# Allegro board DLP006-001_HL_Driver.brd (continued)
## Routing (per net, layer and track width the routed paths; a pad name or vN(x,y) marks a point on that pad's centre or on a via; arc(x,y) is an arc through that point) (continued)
N68109: length 2.3
  TOP w0.254: R31.1 43.69,48.51 43.98,48.81 U4.6
N68463: length 3.8
  TOP w0.254: D7.C 41.17,59.18 C33.2 42.03,57.18 U4.26
N68698: length 3.5
  TOP w0.254: D8.C 45.85,58.19 C32.2 45.97,58.02 45.97,56.79 45.93,56.76 U4.20
N69433: length 1.4
  TOP w0.381: Q6.4 33.94,68.95 R5.2
N70256: length 1.6
  TOP w0.254: Q4.4 40.82,67.31 41.66,68.15 R14.2
N70284: length 7.4
  TOP w0.254: R17.1 49.4,63.88 49.4,63.12 48.38,62.09 48.38,60.72 49.28,59.82 R20.2
  vias: v1(38.35,66.17) v1(39.75,66.17) v1(39.75,64.9) v1(39.75,63.5) v1(40.89,65.53) v1(40.89,64.14) v1(42.29,64.64) v1(42.29,63.12) v1(44.07,64.14) v1(44.07,62.99) v1(45.09,66.29) v1(45.09,64.14) v1(45.09,62.99) v1(46.1,62.99) v1(46.99,66.8) v1(49.53,67.31) v1(50.42,66.55) v1(52.2,66.42)
N70639: length 1.2
  TOP w0.254: R12.2 54.37,69.09 Q7.4
N70965: length 1
  TOP w0.254: R4.2 46.32,68.72 C17.2
N71936: length 1.2
  TOP w0.254: R15.2 C13.2
N87249: length 5.6
  TOP w0.254: R7.2 71.87,68.82 72.67,69.62 R10.1 74.18,69.62 C14.2 74.3,70.61 74.43,70.75 U1.2
N87366: length 3
  TOP w0.254: U1.7 77.68,70.78 78.36,70.1 C16.2
N87373: length 2.6
  TOP w0.254: U1.5 76.38,70.95 76.58,70.75 76.58,70.74 77.09,70.23 C15.2
N87380: length 2.4
  TOP w0.254: R8.1 75.18,70.64 75.08,70.74 U1.3
N87387: length 2.6
  TOP w0.254: U1.16 76.38,79.32 76.71,79.64 C5.2
N87394: length 2.5
  TOP w0.254: U1.17 75.73,80.45 C4.2
N87932: length 12
  TOP w0.254: v1(73.53,81.03) 73.53,80.28 C6.1 73.52,79.51 73.78,79.25 U1.20
  BOTTOM w0.254: v1(73.53,81.03) 72.64,81.92 v1(72.64,89.53)
N88013: length 24.1
  TOP w0.254: R1.1 v1(68.2,98.3) ; v1(74.43,79.38) U1.19
  BOTTOM w0.254: v1(68.2,98.3) 68.2,84.71 73.53,79.38 v1(74.43,79.38)
N88019: length 2.4
  TOP w0.254: U1.18 75.08,79.74 C6.2
N88053: length 19
  TOP w0.254: 73.85,84.9 R2.1 74.8,84.84 75.06,85.09 v1(75.06,86.11)
  TOP w0.305: v1(79.38,79.5) 78.99,79.12 78.99,78.04 U1.12
  TOP w0.762: D3.1 67.18,86.23 ; D3.2 68.45,86.23 ; D3.3 69.72,86.23
  BOTTOM w0.254: v1(79.38,79.5) 79.12,79.76 79.12,82.42 77.72,83.82 77.72,86.74 77.09,87.38 75.69,87.38 75.06,86.74 v1(75.06,86.11)
N88776: length 2.8
  TOP w0.762: D4.1 86.49,81.03 ; 83.95,80.09 83.95,81.03 ; D4.2 85.22,81.03
N88824: length 4.1
  TOP w0.254: R3.2 79.39,80.66 81.96,83.23 Q2.4
N88961: length 6.2
  TOP w0.254: R11.2 81.74,68.07 81.28,68.07 R13.1 80.62,68.55 R6.1 80.06,69.06 C12.2 78.99,70.14 78.99,70.35 78.33,71.01 U1.8
N89225: length 3.6
  TOP w0.254: U1.9 78.98,71 79.25,70.74 79.86,70.74 C12.1 80.96,71.06 C10.1
N89343: length 1.6
  TOP w0.254: C10.2 81.58,69.47 81.18,69.47 R6.2
N14686613: length 1.3
  TOP w0.254: Q5.4 53.05,66.09 R16.2
N14713667: length 8.5
  TOP w0.381: U2.6 16.57,70.29 17.21,70.94 U2.2 17.21,74.36 17.91,75.06 Q3.4
N14713719: length 4.2
  TOP w0.381: 15.92,73.53 U2.4
  TOP w0.508: 15.92,74.55 15.92,73.53
  TOP w1.016: 15.92,76.54 15.92,74.55
  vias: v1(9.78,89.15) v1(9.78,87.5) v1(9.78,85.72) v1(9.78,84.07) v1(9.78,82.42) v1(9.78,80.77) v1(9.78,79.12) v1(11.3,89.15) v1(11.3,87.5) v1(11.3,85.72) v1(11.3,84.07) v1(11.3,82.42) v1(11.3,80.77) v1(11.3,79.12) v1(12.7,89.15) v1(12.7,87.5) v1(12.7,85.72) v1(12.7,84.07) v1(12.7,82.42) v1(12.7,80.77) v1(12.7,79.12) v1(14.22,80.77) v1(14.22,79.12) v1(15.75,80.77) v1(15.75,79.12) v1(17.14,80.77) v1(17.14,79.12)
N14713759: length 3.6
  TOP w0.381: C11.1 17.5,69.7 17.21,69.41 U2.7
N14725098: length 4.7
  TOP w0.254: R47.2 9.68,32.91 9.7,32.93 R44.2 10.54,32.93 11.09,32.38 C54.2 12.73,32.38 13.04,32.07 U5.2
N14726673: length 4.9
  TOP w0.254: R48.2 41.5,32.91 41.53,32.93 R45.2 42.42,32.93 42.96,32.38 C55.2 44.6,32.38 44.9,32.09 45.14,32.09 45.15,32.07 U6.2
N14726919: length 4.9
  TOP w0.254: R49.2 73.3,32.91 73.33,32.93 R46.2 74.3,32.93 74.84,32.38 C56.2 76.48,32.38 76.78,32.09 76.88,32.09 76.89,32.07 U7.2
N14728608:
  vias: v1(18.54,27.43) v1(18.54,25.15) v1(18.54,23.11) v1(18.54,20.83) v1(18.8,18.54) v1(18.8,17.27) v1(19.3,26.16) v1(20.07,27.43) v1(20.07,25.15) v1(20.57,18.54) v1(20.57,17.27) v1(20.83,26.16) v1(21.59,27.43) v1(21.59,25.15) v1(22.35,26.16) v1(22.35,18.54) v1(22.35,17.27) v1(23.11,27.43) v1(23.11,25.15) v1(23.37,23.11) v1(23.37,20.83) v1(23.37,19.3) v1(23.62,17.78) v1(24.89,20.83) v1(24.89,19.43) v1(24.89,18.03) v1(24.89,16.76) v1(26.67,20.83) v1(26.67,19.43) v1(28.32,20.83) v1(28.32,19.43) v1(29.72,20.83) v1(29.72,19.43) v1(30.99,20.07) v1(31.24,18.54) v1(31.24,17.02)
N14729090:
  vias: v1(50.29,27.43) v1(50.29,25.15) v1(50.29,23.11) v1(50.29,20.83) v1(50.55,18.54) v1(50.55,17.27) v1(51.05,26.29) v1(51.82,27.43) v1(51.82,25.15) v1(52.32,18.54) v1(52.32,17.27) v1(52.58,26.29) v1(53.34,27.43) v1(53.34,25.15) v1(54.1,26.29) v1(54.1,18.54) v1(54.1,17.27) v1(54.86,27.43) v1(54.86,25.15) v1(55.12,23.11) v1(55.12,20.83) v1(55.12,19.3) v1(55.37,17.78) v1(56.64,20.83) v1(56.64,19.43) v1(56.64,18.03) v1(56.64,16.76) v1(58.42,20.83) v1(58.42,19.43) v1(60.07,20.83) v1(60.07,19.43) v1(61.47,20.83) v1(61.47,19.43) v1(62.74,20.07) v1(62.99,18.54) v1(62.99,17.02)
N14729291:
  vias: v1(82.3,27.43) v1(82.3,25.15) v1(82.3,23.11) v1(82.3,20.83) v1(82.55,18.54) v1(82.55,17.27) v1(83.06,26.16) v1(83.82,27.43) v1(83.82,25.15) v1(84.33,18.54) v1(84.33,17.27) v1(84.58,26.16) v1(85.34,27.43) v1(85.34,25.15) v1(86.11,26.16) v1(86.11,18.54) v1(86.11,17.27) v1(86.87,27.43) v1(86.87,25.15) v1(87.12,23.11) v1(87.12,20.83) v1(87.12,19.3) v1(87.38,17.78) v1(88.65,20.83) v1(88.65,19.43) v1(88.65,18.03) v1(88.65,16.76) v1(90.42,20.83) v1(90.42,19.43) v1(92.08,20.83) v1(92.08,19.43) v1(93.47,20.83) v1(93.47,19.43) v1(94.74,20.07) v1(95,18.54) v1(95,17.02)
N14733774: length 1.8
  TOP w0.254: R24.1 17.21,50.24 U3.3
N14733778: length 1.8
  TOP w0.254: U3.2 R23.1
N14755460: length 2.2
  TOP w0.381: U2.1 19.01,72.3 19.18,72.14 C11.2
N14772112:
  vias: v1(13.46,98.04) v1(13.46,96.52) v1(15.11,98.04) v1(15.11,96.52) v1(18.8,98.04) v1(18.8,96.52) v1(20.45,98.04) v1(20.45,96.52)
N14778799: length 29
  TOP w0.254: U1.4 75.73,70.83 75.95,70.61 v1(75.95,70.48) 76.07,70.36 R9.2
  TOP w0.508: SW1.5 v1(91.19,84.32)
  BOTTOM w0.508: v1(91.19,84.32) 91.19,77.47 84.2,70.48 v1(75.95,70.48)
N14789264: length 1.1
  TOP w0.254: C65.1 R61.2
N14790575: length 1.1
  TOP w0.254: C63.1 R59.2
N14791153: length 1.1
  TOP w0.254: C64.1 R60.2
N14801227: length 0.9
  TOP w0.254: C71.1 R64.2
N14802192: length 3
  TOP w0.254: U4.14 49.18,49.06 49,48.88 48.68,48.88 48.53,49.02 U4.13
N14805188: length 19.9
  TOP w0.508: v1(97.44,20.45) Q10.1 ; R58.2 v1(84.82,29.4)
  BOTTOM w0.508: v1(97.44,20.45) 97.44,21.18 89.22,29.4 v1(84.82,29.4)
N14810522: length 19.5
  TOP w0.508: R57.2 v1(52.95,29.4) ; Q9.1 v1(65.57,20.67)
  BOTTOM w0.508: v1(52.95,29.4) 57.47,29.4 65.57,21.3 v1(65.57,20.67)
N14810532: length 20.1
  TOP w0.508: v1(33.69,20.45) Q8.1 ; v1(21.21,29.4) R56.2
  BOTTOM w0.508: v1(33.69,20.45) 33.69,21.56 25.84,29.4 v1(21.21,29.4)
N14814395: length 0.9
  TOP w0.254: C70.1 R63.2
N14818963: length 2.3
  TOP w0.254: J5.7 7.07,55.59 L8.1
N14818967: length 2.3
  TOP w0.254: J5.8 7.05,56.59 L7.1
N14818971: length 2.3
  TOP w0.254: J5.9 7.04,57.59 L6.1
N14901904: length 0.9
  TOP w0.254: C69.1 R62.2
N15037743: length 2.3
  TOP w0.254: C45.2 45.59,48.59 45.28,48.9 U4.8
N15077521: length 1.4
  TOP w0.254: Q1.4 66.41,96.89 R1.2

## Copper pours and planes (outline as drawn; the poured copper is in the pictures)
16V_REG on TOP (solid shape): 57.68,65.53 55.35,65.53 55.35,68.12 57.68,68.12
16V_REG on TOP: 58.93,67.44 58.17,68.2 55.37,68.2 54.99,67.82 54.99,63.63 55.63,62.99 66.04,62.99 68.83,60.2 77.85,60.2 77.85,65.79 77.09,66.55 61.59,66.55 60.71,67.44
16V_REG on TOP: 18.52,33.78 17.96,33.22 17.96,32.46 19.18,32.46 19.49,32.77 27.89,32.77 31.11,35.99 31.11,37.08 27.75,40.44 26.87,40.44 24.04,37.62 19.96,37.62 19.59,37.24 19.59,34.3 19.07,33.78
16V_REG on TOP: 51.45,34.84 49.83,33.22 49.83,32.46 51.09,32.46 51.39,32.77 59.77,32.77 62.99,35.99 62.99,37.08 59.49,40.58 58.89,40.58 55.92,37.62 51.99,37.62 51.45,37.07
16V_REG on TOP: 83.32,34.83 81.71,33.22 81.71,32.46 83.13,32.46 83.44,32.77 91.64,32.77 94.87,35.99 94.87,36.07 96.52,36.07 99.06,38.61 99.06,39.37 96.9,41.53 95.89,41.53 94.61,40.26 89.92,40.26 87.27,37.62 83.72,37.62 83.32,37.22
16V_REG on BOTTOM: 25.91,42.67 21.97,38.73 19.56,38.73 17.91,37.08 17.91,33.27 18.54,32.64 32.89,32.64 33.91,33.66 33.91,40.13 31.37,42.67
16V_REG on BOTTOM: 54.48,39.24 52.45,39.24 47.88,34.67 47.88,33.5 49.89,31.5 65.66,31.5 67.31,33.15 67.31,35.81 60.83,42.29 57.53,42.29
16V_REG on BOTTOM: 76.33,66.55 63.5,66.55 63.25,66.29 63.25,63.5 63.5,63.25 76.2,63.25 76.71,63.75 76.71,66.17
16V_REG on BOTTOM: 86.87,38.23 83.69,38.23 79.76,34.29 79.76,33.5 81.76,31.5 97.28,31.5 99.31,33.53 99.31,42.16 98.93,42.55 91.19,42.55
16V_REG on L3_PWR: 29.84,32.51 31.11,33.78 52.07,33.78 53.59,32.26 60.2,32.26 62.1,34.16 83.44,34.16 85.34,32.26 99.31,32.26 99.31,40.77 89.66,50.42 89.66,65.15 86.61,68.2 56.13,68.2 48.9,60.96 19.18,60.96 19.18,48.26 12.83,41.91 12.83,33.66 13.97,32.51
GND_SIGNAL on TOP: outline of 87 points within 0.51,0.76 97.66,45.72
GND_SIGNAL on TOP: 75.31,29.21 75.31,30.35 75.95,30.35 76.33,30.73 78.11,30.73 78.11,36.83 77.85,37.08 76.83,37.08 76.57,36.82 76.57,34.02 76.33,33.78 73.53,33.78 73.53,37.08 65.28,45.34 53.59,45.34 52.07,46.86 52.07,50.55 51.31,51.31 49.66,51.31 49.66,54.61 50.8,54.61 51.05,54.86 51.05,59.56 49.85,60.77 52.51,63.44 53.98,61.98 66.04,61.98 66.04,59.56 67.69,57.91 77.72,57.91 78.36,58.55 78.36,66.17 77.98,66.55 77.98,68.07 80.01,68.07 80.77,67.31 83.82,67.31 83.82,46.35 95,46.35 96.9,44.45 96.9,43.94 94.9,41.94 93.19,41.94 93.19,41.93 89.05,41.93 85.72,38.61 83.44,38.61 81.41,36.58 81.41,29.46 81.15,29.21
GND_SIGNAL on TOP: 21.59,61.98 38.35,61.98 38.73,61.59 38.73,55.17 39.29,54.61 40.16,54.61 40.13,54.58 40.13,51.28 38.61,51.28 38.61,49.91 37.59,49.91 37.47,50.04 37.47,51.03 37.21,51.28 28.4,51.28 26.34,53.34 21.46,53.34 20.95,53.85 20.95,61.34
GND_SIGNAL on TOP: 32.77,94.49 32.77,97.28 33.4,97.92 36.7,97.92 37.47,97.16 37.47,94.87 35.56,94.87 35.18,94.49
GND_SIGNAL on TOP: 12.57,30.73 14.35,30.73 14.35,36.96 14.1,37.21 13.08,37.21 12.81,36.94 12.81,34.02 12.57,33.78 9.91,33.78 9.91,37.21 16.64,43.94 24.26,43.94 25.53,42.67 25.53,42.16 21.97,38.61 19.68,38.61 17.65,36.58 17.65,29.46 17.4,29.21 11.56,29.21 11.56,30.35 12.19,30.35
GND_SIGNAL on TOP: 42.55,46.61 42.16,46.23 42.16,44.96 42.42,44.7 47.62,44.7 47.75,44.83 47.75,45.34 47.37,45.34 47.12,45.59 47.12,46.35 46.86,46.61
GND_SIGNAL on TOP: 1.02,97.54 1.02,78.99 1.52,78.49 5.71,78.49 8.89,75.31 10.54,75.31 10.54,76.07 7.11,79.5 7.11,92.33 8,93.22 11.05,93.22 11.05,94.74 9.53,96.27 9.53,97.66 1.14,97.66
GND_SIGNAL on TOP: 44.45,30.73 46.23,30.73 46.23,36.83 45.97,37.08 44.96,37.08 44.69,36.82 44.69,34.02 44.45,33.78 41.66,33.78 41.66,42.42 43.05,43.81 56.26,43.81 57.4,42.67 57.4,42.16 53.85,38.61 51.56,38.61 49.53,36.58 49.53,29.46 49.28,29.21 43.69,29.21 43.31,29.59 43.31,30.35 44.07,30.35
GND_SIGNAL on TOP: 81.41,83.69 82.68,83.69 82.68,86.74 82.17,87.25 78.11,87.25 76.58,85.72 76.58,83.82 76.33,83.57 70.87,83.57 69.72,82.42 69.72,74.93 70.99,73.66 81.66,73.66 81.66,76.45 73.41,76.45 72.9,76.96 72.9,81.28 73.28,81.66 79.38,81.66
GND_SIGNAL on BOTTOM: 0.51,96.65 0.51,80.01 2.03,78.49 8,78.49 8,90.55 10.92,93.47 10.92,98.81 10.16,99.57 3.43,99.57
GND_SIGNAL on BOTTOM: 37.21,59.82 34.67,59.82 34.42,59.56 34.42,53.47 37.47,50.42 49.15,50.42 50.29,51.56 50.29,54.23 49.02,55.5 41.53,55.5
GND_SIGNAL on BOTTOM: 29.21,59.05 25.4,62.87 15.24,62.87 14.61,62.23 14.61,55.24 21.59,48.26 27.3,48.26 29.21,50.16
GND_SIGNAL on BOTTOM: 51.94,59.56 51.94,45.09 61.21,45.09 72.77,33.53 78.36,33.53 83.57,38.73 86.61,38.73 90.93,43.05 98.17,43.05 99.31,44.2 99.31,97.16 97.03,99.44 74.68,99.44 73.41,98.17 73.41,88.52 74.04,87.88 77.6,87.88 78.23,87.25 78.23,83.95 80.14,82.04 80.14,79.12 79.5,78.49 71.75,78.49 71.25,77.98 71.25,74.68 72.77,73.15 72.77,70.23 71.63,69.09 58.42,69.09 56.52,67.18 56.52,64.14
GND_SIGNAL on BOTTOM: 85.47,3.68 84.84,3.05 73.28,3.05 68.96,7.37 68.96,14.35 67.18,16.13 54.1,16.13 53.59,15.62 53.59,4.19 52.58,3.17 40.89,3.17 36.7,7.37 36.7,14.61 35.18,16.13 22.23,16.13 21.72,15.62 21.72,3.81 20.83,2.92 20.7,3.05 9.14,3.05 4.95,7.24 4.95,64.52 4.45,65.02 1.27,65.02 0.76,64.52 0.76,3.17 3.17,0.76 96.9,0.76 99.31,3.17 99.31,15.24 98.42,16.13 86.11,16.13 85.47,15.49
GND_SIGNAL on BOTTOM: 56.52,43.94 35.94,43.94 34.92,42.93 34.92,36.58 36.07,35.43 38.73,35.43 41.02,33.15 45.72,33.15 52.2,39.62 54.36,39.62 57.02,42.29 57.02,43.43
GND_SIGNAL on L2_GND: 0.76,99.31 99.31,99.31 99.31,0.64 0.76,0.64
GND_SIGNAL on L3_PWR: 0.76,99.31 99.31,99.31 99.31,0.64 0.76,0.64 ; 5 cut-outs
VBATT on TOP, BOTTOM: 13.84,74.3 7.87,74.3 4.95,77.22 1.52,77.22 1.14,76.83 1.14,66.42 1.91,65.66 13.97,65.66 14.35,66.04 14.35,73.79
VBATT on L3_PWR: 13.84,77.22 0.76,77.22 0.76,65.66 13.97,65.66 14.35,66.04 14.35,76.71
VIN_HEATER on TOP: 50.42,92.71 44.32,92.71 43.69,93.34 43.69,96.52 44.32,97.16 50.93,97.16 50.93,93.22
VIN_HEATER on BOTTOM: 49.66,97.03 48.77,97.92 44.58,97.92 43.69,97.03 43.69,92.08 44.32,91.44 48.64,91.44 49.66,92.46
VIN_MAIN on TOP: 30.86,93.85 40.39,93.85 40.39,91.19 39.12,89.92 31.75,89.92 30.86,90.81
VIN_MAIN on BOTTOM: 40.13,93.85 33.15,93.85 31.5,92.2 31.5,90.04 32.26,89.28 39.12,89.28 40.13,90.3
SW1 on TOP (solid shape): 40.67,68.28 38.33,68.28 38.33,70.87 40.67,70.87
SW1 on TOP: 44.2,87.63 33.15,87.63 31.11,85.6 31.11,73.28 34.54,69.85 34.54,68.58 37.34,68.58 37.72,68.2 40.89,68.2 41.66,68.96 44.7,68.96 45.72,69.98 46.61,69.98 46.61,70.99 45.09,72.52 45.09,86.74
SW1 on BOTTOM: 43.31,71.25 33.02,71.25 31.37,72.9 31.37,75.56 32,76.2 43.05,76.2 43.94,75.31 43.94,71.88
SW1 on L3_PWR: 44.2,87.63 33.15,87.63 31.11,85.6 31.11,71.63 33.78,68.96 44.7,68.96 45.09,69.34 45.09,86.74
SW2 on TOP (solid shape): 53.24,68.28 50.9,68.28 50.9,70.87 53.24,70.87
SW2 on TOP: 56.01,68.58 56.01,69.98 55.75,70.23 54.1,70.23 53.72,69.85 53.72,68.58 53.47,68.33 50.55,68.33 46.99,71.88 46.99,86.61 48.01,87.63 60.2,87.63 61.34,86.49 61.34,74.8 62.36,73.79 62.36,69.6 61.72,69.6 61.21,69.09 58.8,69.09 58.29,68.58
SW2 on BOTTOM: 61.72,76.07 49.91,76.07 49.28,75.44 49.28,71.5 49.66,71.12 61.98,71.12 62.48,71.63 62.48,75.31
SW2 on L3_PWR: 50.04,68.83 46.99,71.88 46.99,86.61 48.01,87.63 61.85,87.63 62.61,86.87 62.61,69.34 62.1,68.83
V_BATT_PROT on TOP (solid shape): 36.22,65.53 33.88,65.53 33.88,68.12 36.22,68.12
V_BATT_PROT on TOP (solid shape): 21.98,78.95 24.11,78.95 24.11,79.42 24.55,79.42 24.55,74.5 24.11,74.5 24.11,74.97 21.98,74.97 21.98,74.38 21.45,74.38 21.45,74.97 20.53,74.97 20.53,78.95 21.45,78.95 21.45,79.54 21.98,79.54
V_BATT_PROT on TOP (solid shape): 65.68,94.41 62.98,94.41 62.98,95.08 63.47,95.08 63.47,95.39 62.98,95.39 62.98,95.73 63.47,95.73 63.47,96.04 62.98,96.04 62.98,96.39 63.47,96.39 63.47,96.69 62.98,96.69 62.98,97.36 65.68,97.36
V_BATT_PROT on TOP: 21.34,80.26 25.4,80.26 26.42,81.28 26.42,93.98 30.23,93.98 30.23,68.96 30.99,68.2 36.2,68.2 36.96,67.44 36.96,66.04 38.48,64.52 38.48,63.12 38.35,62.99 19.56,62.99 17.65,64.9 17.65,68.58 19.56,68.58 20.55,69.57 20.55,79.48
V_BATT_PROT on TOP: 73.91,72.9 70.48,72.9 67.69,75.69 67.69,83.19 65.53,85.34 65.53,98.68 65.15,99.06 53.34,99.06 51.82,97.54 51.82,92.2 54.1,89.92 58.67,89.92 61.85,86.74 61.85,75.56 62.99,74.42 62.99,71.63 64.9,69.72 71.75,69.72 71.75,70.23 72.77,71.25 73.91,71.25
V_BATT_PROT on TOP: 36.7,49.28 36.7,50.67 36.45,50.93 34.04,50.93 33.53,50.42 33.53,49.53 33.78,49.28
V_BATT_PROT on TOP: 32.13,94.61 32.13,98.42 31.62,98.93 27.05,98.93 26.42,98.3 26.42,93.98 30.23,93.98 30.86,94.61
V_BATT_PROT on BOTTOM: 29.84,92.71 29.84,89.92 31.5,88.27 46.99,88.27 52.2,93.47 52.2,98.3 53.09,99.19 65.02,99.19 65.53,98.68 65.53,85.34 70.55,80.33 70.55,74.49 72.26,72.77 72.26,70.99 71.37,70.1 64.77,70.1 64.14,70.74 64.14,75.18 61.85,77.47 30.48,77.47 29.84,76.83 29.84,71.75 34.04,67.56 34.04,52.96 35.56,51.44 35.56,48.26 34.92,47.62 31.75,47.62 29.84,49.53 29.84,59.05 25.53,63.37 19.3,63.37 18.41,64.26 18.41,73.15 24.13,78.87 24.13,97.16 26.04,99.06 31.75,99.06 32.38,98.42 32.38,95.25
V_BATT_PROT on L3_PWR: 30.48,86.11 30.48,71.75 35.43,66.8 35.43,62.48 34.67,61.72 19.18,61.72 19.18,91.82 26.54,99.19 68.71,99.19 70.87,97.03 70.87,74.3 73.15,72.01 73.15,69.6 72.52,68.96 63.88,68.96 63.25,69.6 63.25,87.38 62.36,88.27 32.64,88.27
V_FAN on TOP (solid shape): 86.86,78.2 87.36,78.2 87.36,77.3 86.86,77.3 86.86,74.1 86.11,74.1 86.11,74.59 83.05,74.59 83.05,74.1 82.3,74.1 82.3,77.3 81.81,77.3 81.81,78.2 82.3,78.2 82.3,78.63 86.86,78.63
V_FAN on TOP: 82.42,78.49 89.92,78.49 93.34,75.06 93.34,47.88 92.71,47.24 86.87,47.24 85.98,48.13 85.98,67.82 82.42,71.37
V_LED_0 on TOP (solid shape): 77.52,9.13 77.05,9.13 77.05,7 77.64,7 77.64,6.47 77.05,6.47 77.05,5.55 73.07,5.55 73.07,6.47 72.48,6.47 72.48,7 73.07,7 73.07,9.13 72.6,9.13 72.6,9.57 77.52,9.57
V_LED_0 on TOP: 71.5,16.76 71.5,4.83 84.45,4.83 84.96,5.33 84.96,8.26 84.2,9.02 84.2,13.34 84.45,13.59 84.96,13.59 84.96,15.29 77.55,15.29 76.58,16.26 76.58,28.14 76.33,28.4 70.87,28.4 70.23,27.76 70.23,18.03
V_LED_0 on BOTTOM: 70.48,28.57 70.1,28.19 70.1,8 73.41,4.7 83.95,4.7 84.96,5.71 84.96,15.49 84.33,16.13 81.79,16.13 79.88,18.03 79.88,27.69 78.99,28.57
V_LED_0 on L3_PWR: 71.5,16.76 71.5,7.87 72.52,6.86 72.52,4.83 84.71,4.83 84.71,8.51 84.2,9.02 84.2,13.34 84.45,13.59 84.96,13.59 84.96,15.29 77.55,15.29 76.58,16.26 76.58,28.14 76.33,28.4 70.87,28.4 70.23,27.76 70.23,18.03
V_LED_1 on TOP (solid shape): 13.76,9.13 13.29,9.13 13.29,7 13.88,7 13.88,6.47 13.29,6.47 13.29,5.55 9.31,5.55 9.31,6.47 8.72,6.47 8.72,7 9.31,7 9.31,9.13 8.84,9.13 8.84,9.57 13.76,9.57
V_LED_1 on TOP: 7.75,16.76 7.75,4.83 20.7,4.83 21.21,5.33 21.21,8.26 20.45,9.02 20.45,13.34 20.7,13.59 21.21,13.59 21.21,15.24 21.16,15.29 13.79,15.29 12.83,16.26 12.83,28.14 12.57,28.4 7.11,28.4 6.48,27.76 6.48,18.03
V_LED_1 on BOTTOM: 6.73,28.57 6.35,28.19 6.35,8.64 10.29,4.7 20.19,4.7 21.21,5.71 21.21,15.49 20.57,16.13 18.03,16.13 16.13,18.03 16.13,27.69 15.24,28.57
V_LED_1 on L3_PWR: 7.75,16.76 7.75,7.87 8.76,6.86 8.76,4.83 20.95,4.83 20.95,8.51 20.45,9.02 20.45,13.34 20.7,13.59 21.21,13.59 21.21,15.24 21.16,15.29 13.79,15.29 12.83,16.26 12.83,28.14 12.57,28.4 7.11,28.4 6.48,27.76 6.48,18.03
V_LED_2 on TOP (solid shape): 45.64,9.13 45.17,9.13 45.17,7 45.76,7 45.76,6.47 45.17,6.47 45.17,5.55 41.19,5.55 41.19,6.47 40.6,6.47 40.6,7 41.19,7 41.19,9.13 40.72,9.13 40.72,9.57 45.64,9.57
V_LED_2 on TOP: 39.62,16.76 39.62,4.83 52.58,4.83 53.09,5.33 53.09,8.26 52.32,9.02 52.32,13.34 52.58,13.59 53.09,13.59 53.09,15.29 45.67,15.29 44.7,16.26 44.7,28.14 44.45,28.4 38.99,28.4 38.35,27.76 38.35,18.03
V_LED_2 on BOTTOM: 38.61,28.57 38.23,28.19 38.23,8 41.53,4.7 52.07,4.7 53.09,5.71 53.09,15.49 52.45,16.13 49.91,16.13 48.01,18.03 48.01,27.69 47.12,28.57
V_LED_2 on L3_PWR: 39.62,16.76 39.62,7.87 40.64,6.86 40.64,4.83 52.83,4.83 52.83,8.51 52.32,9.02 52.32,13.34 52.58,13.59 53.09,13.59 53.09,15.29 45.67,15.29 44.7,16.26 44.7,28.14 44.45,28.4 38.99,28.4 38.35,27.76 38.35,18.03
N57763 on TOP: 30.38,30.45 32.69,32.77 33.15,32.77 35.18,30.73 35.18,25.65 32.38,25.65 32.38,27.94 30.38,29.95
N57763 on BOTTOM: 35.56,30.99 31.75,30.99 30.61,29.84 30.61,27.3 31.11,26.8 36.07,26.8 36.45,27.18 36.45,30.1
N57763 on L3_PWR: 30.38,30.45 31.8,31.88 34.04,31.88 35.18,30.73 35.18,25.65 32.38,25.65 32.38,27.18 30.38,29.18
N60948 on TOP: 62.26,30.45 64.57,32.77 65.02,32.77 67.06,30.73 67.06,25.65 64.26,25.65 64.26,27.94 62.26,29.95
N60948 on BOTTOM: 67.69,30.61 63.88,30.61 62.74,29.46 62.74,26.92 63.25,26.42 68.2,26.42 68.58,26.8 68.58,29.72
N60948 on L3_PWR: 62.26,30.45 63.55,31.75 66.04,31.75 67.06,30.73 67.06,25.65 64.26,25.65 64.26,27.69 62.26,29.69
N64418 on TOP: 94.13,30.45 96.44,32.77 96.9,32.77 98.93,30.73 98.93,25.65 96.14,25.65 96.14,27.94 94.13,29.95
N64418 on BOTTOM: 98.3,30.48 94.49,30.48 93.34,29.34 93.34,26.8 93.85,26.29 98.81,26.29 99.19,26.67 99.19,29.59
N64418 on L3_PWR: 94.13,31.39 94.49,31.75 97.92,31.75 98.93,30.73 98.93,25.65 96.14,25.65 96.14,27.18 94.13,29.18
N66768 on TOP: 37.97,47.24 39.12,47.24 39.5,47.62 39.5,48.9 39.37,49.02 37.97,49.02
N66777 on TOP: 38.48,46.74 35.69,46.74 35.69,45.34 35.81,45.21 37.97,45.21 38.48,45.72
N70284 on TOP: 39.88,62.36 39.12,63.12 39.12,64.52 37.72,65.91 37.72,67.69 37.97,67.94 40.01,67.94 40.01,66.55 40.51,66.04 42.04,66.04 42.29,66.29 42.29,67.44 42.67,67.82 52.58,67.82 52.58,66.29 52.45,66.17 50.16,66.17 46.35,62.36
N70284 on BOTTOM: 50.29,70.36 40.01,70.36 39.37,69.72 39.37,63.25 40.13,62.48 47.5,62.48 50.93,65.91 50.93,69.72
N70284 on L3_PWR: 37.97,68.2 37.47,67.69 37.47,62.48 38.1,61.85 48.26,61.85 53.34,66.93 53.34,67.69 52.83,68.2
N87932 on TOP (solid shape): 67.56,92.8 70.62,92.8 70.62,93.29 71.37,93.29 71.37,90.09 71.86,90.09 71.86,89.19 71.37,89.19 71.37,88.76 66.81,88.76 66.81,89.19 66.31,89.19 66.31,90.09 66.81,90.09 66.81,93.29 67.56,93.29
N87932 on TOP: 66.8,93.6 66.8,88.77 75.56,88.77 76.45,89.66 76.45,96.9 75.18,98.17 69.34,98.17 67.56,96.39 66.04,96.39 66.04,94.36
N88053 on TOP: 66.8,86.49 66.8,84.96 67.69,84.07 74.55,84.07 74.55,85.72 73.79,86.49
N88776 on TOP (solid shape): 85.74,85 85.24,85 85.24,84.7 85.74,84.7 85.74,84.35 85.24,84.35 85.24,84.05 85.74,84.05 85.74,83.69 85.24,83.69 85.24,83.4 85.74,83.4 85.74,82.73 83.03,82.73 83.03,85.67 85.74,85.67
N88776 on TOP: 83.06,88.77 82.04,89.79 82.04,94.11 87,94.11 89.15,91.95 89.15,81.53 88.52,80.9 83.57,80.9 83.06,81.41
N14713719 on TOP: 8.51,91.69 8.51,78.99 11.18,76.33 13.97,76.33 14.48,75.82 19.3,75.82 19.81,76.33 19.81,79.88 20.83,80.9 24.89,80.9 25.65,81.66 25.65,91.69
N14713719 on BOTTOM: 21.59,90.81 10.79,90.81 8.89,88.9 8.89,78.74 10.16,77.47 21.59,77.47 23.5,79.38 23.5,88.9
N14713719 on L3_PWR: 17.65,92.2 9.78,92.2 8.38,90.81 8.38,78.61 9.02,77.98 17.02,77.98 18.29,79.25 18.29,91.57
N14728608 on TOP: 17.91,28.14 30.66,28.14 31.7,27.1 31.7,19.02 32.64,18.08 32.64,16.76 32.51,16.64 31.75,16.64 31.11,16 31.11,14.73 30.61,14.22 25.02,14.22 24.77,14.48 24.77,16.26 24.26,16.76 17.91,16.76 17.65,17.02 17.65,27.89
N14728608 on BOTTOM: 24.64,28.45 17.53,28.45 16.76,27.69 16.76,18.16 18.29,16.64 32.13,16.64 32.77,17.27 32.77,20.32
N14728608 on L3_PWR: 17.91,28.14 24.94,28.14 31.7,21.39 31.7,19.02 32.64,18.08 32.64,16.76 32.51,16.64 31.75,16.64 31.11,16 31.11,14.73 30.61,14.22 25.02,14.22 24.77,14.48 24.77,16.26 24.26,16.76 17.91,16.76 17.65,17.02 17.65,27.89
N14729090 on TOP: 49.78,28.14 62.53,28.14 63.58,27.1 63.58,19.02 64.52,18.08 64.52,16.76 64.39,16.64 63.63,16.64 62.99,16 62.99,14.73 62.48,14.22 56.9,14.22 56.64,14.48 56.64,16.26 56.13,16.76 49.78,16.76 49.53,17.02 49.53,27.89
N14729090 on BOTTOM: 56.64,28.45 49.53,28.45 48.77,27.69 48.77,18.16 50.29,16.64 64.14,16.64 64.77,17.27 64.77,20.32
N14729090 on L3_PWR: 49.78,28.14 56.95,28.14 63.58,21.52 63.58,19.02 64.52,18.08 64.52,16.76 64.39,16.64 63.63,16.64 62.99,16 62.99,14.73 62.48,14.22 56.9,14.22 56.64,14.48 56.64,16.26 56.13,16.76 49.78,16.76 49.53,17.02 49.53,27.89
N14729291 on TOP: 81.66,28.14 94.41,28.14 95.45,27.1 95.45,19.02 96.39,18.08 96.39,16.76 96.27,16.64 95.25,16.64 94.87,16.26 94.87,14.73 94.36,14.22 88.77,14.22 88.52,14.48 88.52,16.26 88.01,16.76 81.66,16.76 81.41,17.02 81.41,27.89
N14729291 on BOTTOM: 88.65,28.45 81.53,28.45 80.77,27.69 80.77,18.16 82.3,16.64 96.14,16.64 96.77,17.27 96.77,20.32
N14729291 on L3_PWR: 81.66,28.14 88.95,28.14 95.45,21.64 95.45,19.02 96.39,18.08 96.39,16.76 96.27,16.64 95.25,16.64 94.87,16.26 94.87,14.73 94.36,14.22 88.77,14.22 88.52,14.48 88.52,16.26 88.01,16.76 81.66,16.76 81.41,17.02 81.41,27.89
N14772112 on TOP: 11.81,95.5 22.99,95.5 22.99,98.93 11.81,98.93 11.3,98.42 11.3,96.01
N14772112 on BOTTOM: 22.23,99.06 13.34,99.06 12.06,97.79 12.06,94.61 13.34,93.34 21.59,93.34 23.5,95.25 23.5,97.79
N14772112 on L3_PWR: 21.46,99.06 13.34,99.06 12.06,97.79 12.06,94.61 13.34,93.34 19.56,93.34 22.23,96.01 22.23,98.3

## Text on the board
BOTTOM: LAYER 4 - BOTTOM | 4
Ref Des/Assembly Bottom: ASSEMBLY BOTTOM
Board Geometry/Soldermask Bottom: 6
Package Geometry/Pastemask Bottom: PASTEMASK BOTTOM | 12
Ref Des/Silkscreen Bottom: 9
TOP: LAYER 1 - TOP | 1
Ref Des/Assembly Top: ASSEMBLY TOP
Board Geometry/Soldermask Top: 5
Package Geometry/Pastemask Top: PASTEMASK TOP | 8
Ref Des/Silkscreen Top: SHUNT | TEXAS INSTRUMENTS | SCH 2515624 REV[C] | PCB 2515625 REV[C] | CCA 2515626 REV[C] | DLP006 | DLP5531-Q1 EVM | HEADLIGHT DRIVER | FAN | OFF | ON | INPUT | POWER | FORMATTER | POWER OUT | FOR EVALUATION ONLY | NOT FCC APPROVED | FOR RESALE | FAN ENABLE | HEADLIGHT | DRIVER | INTERFACE | HOT | 7 | LED0 | LED1 | LED2 | S/N
L2_GND: LAYER 2 - GND | 2
L3_PWR: LAYER 3 - SIGNAL | 3
DIMENSION: 10 | VIAS ARE TENTED OVER ON TOP SIDE ONLY (DESIGN INTENT). | 0.062" +/- 10 % | PREPREG (2 sheets of .0035) | .039 CORE | LAYER STACKUP | SILKSCREEN PRIMARY SIDE | SOLDERMASK PRIMARY SIDE | LAYER 1 PRIMARY SIDE | LAYER 2 (GND) | LAYER 3 (PWR) | LAYER 4 SECONDARY SIDE | SOLDERMASK SECONDARY SIDE | SILKSCREEN SECONDARY SIDE | LAYER DEFINITION | FINISH | Cu WT. | 2 oz | COMPONENT SIDE VIEW
PAGE_OUTLINE: LAYER 13 - FAB
User.12: OF | 10
User.22: 12.0 | 14.0 | 42.0 | 47.24 | 157.0 | 51.18 | +0.0/-12.0 | +3.0/-3.0 | +1.97/-1.97 | PLATED | NON-PLATED | 1064 | 32 | 8 | 30 | 4 | FIGURE | SIZE(Finished) | DRILL CHART: TOP to BOTTOM | ALL UNITS ARE IN MILS | TOLERANCE | PLATING | QTY
